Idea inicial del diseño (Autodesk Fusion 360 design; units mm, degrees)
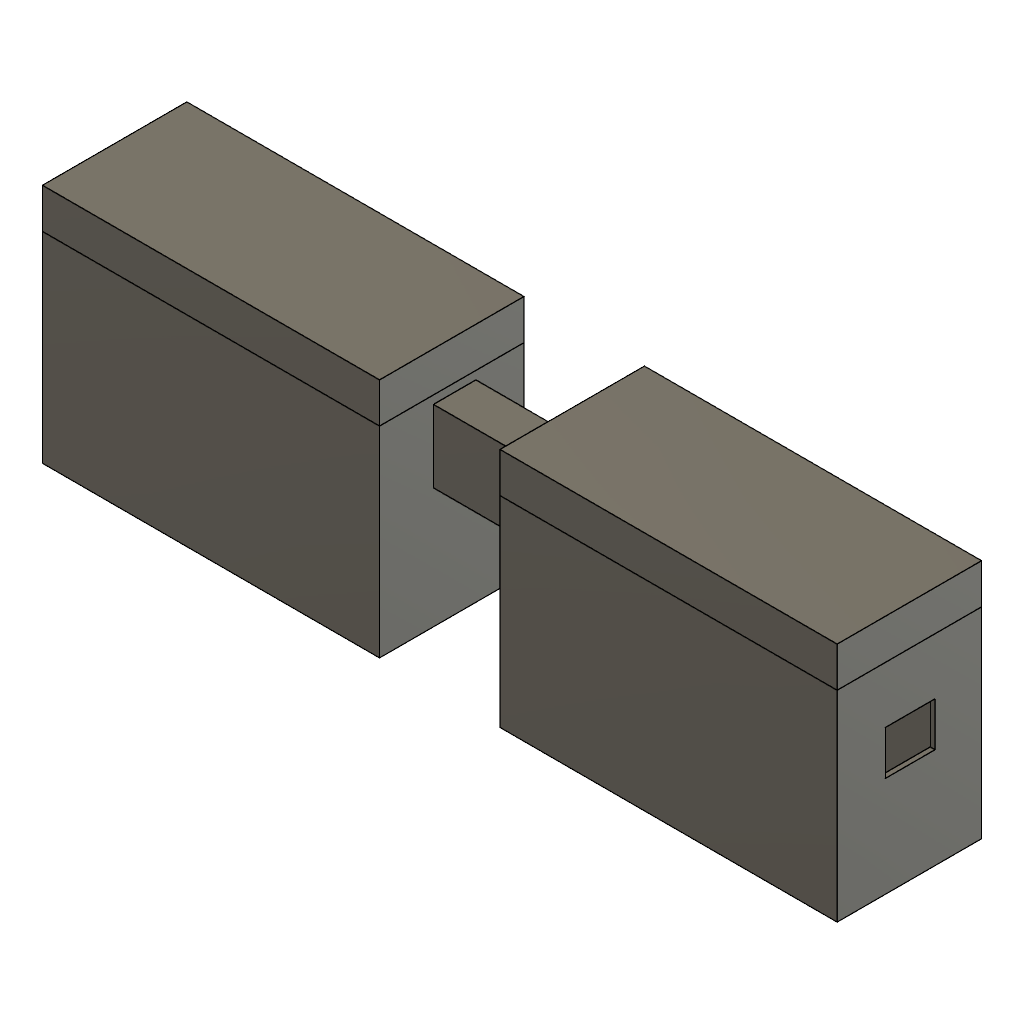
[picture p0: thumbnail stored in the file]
part number: 2026-10-15-12-44-03-142
sketch "Boceto2" plane through (0, 0, 0) normal (0, 0, 1) x axis (1, 0, 0)
  line L1 (40, 30) -> (-30, 30)
  line L2 (40, -20) -> (40, 30)
  line L3 (-30, -20) -> (40, -20)
  line L4 (-30, 30) -> (-30, -20)
  horizontal L1
  vertical L2
  horizontal L3
  vertical L4
extrude "Extruir3" new body sketch "Boceto2" along normal blind 30
move "Desplazar2"
sketch "Boceto4" plane through (40, 0, 0) normal (1, 0, 0) x axis (0, 0, -1)
  line L1 (0, 50) -> (0, 0)
  line L2 (-30, 50) -> (0, 50)
  line L3 (-30, 0) -> (-30, 50)
  line L4 (0, 0) -> (-30, 0)
copy_paste_bodies "CopiarPegarCuerpos"
move "Desplazar3"
sketch "Boceto5" plane through (65, 0, 0) normal (-1, 0, 0) x axis (0, 0, 1)
  line L1 (0, 0) -> (0, 50)
  line L2 (30, 0) -> (0, 0)
  line L3 (30, 50) -> (30, 0)
  line L4 (0, 50) -> (30, 50)
  line L5 (18.8114, 40) -> (10, 40)
  line L6 (18.8114, 25) -> (18.8114, 40)
  line L7 (10, 25) -> (18.8114, 25)
  line L8 (10, 40) -> (10, 25)
  horizontal L5
  vertical L6
  horizontal L7
  vertical L8
shell "Vaciado3" innerThickness 1
shell "Vaciado4" innerThickness 1
sketch "Boceto6" plane through (40, 0, 0) normal (1, 0, 0) x axis (0, 0, -1)
  line L1 (-10, 39.9144) -> (-18.6267, 39.9144)
  line L2 (-10, 25) -> (-10, 39.9144)
  line L3 (-18.6267, 25) -> (-10, 25)
  line L4 (-18.6267, 39.9144) -> (-18.6267, 25)
  horizontal L1
  vertical L2
  horizontal L3
  vertical L4
extrude "Extruir4" cut sketch "Boceto6" along normal blind 35 and against normal blind 10
extrude "Extruir5" new body sketch "Boceto5" profile of L5 L6 L7 L8 along normal blind 25
sketch "Boceto7" plane through (0, 0, 10) normal (0, 0, -1) x axis (-1, 0, 0)
  line L1 (-65, 25) -> (-65, 40)
  line L2 (-40, 25) -> (-65, 25)
  line L3 (-40, 40) -> (-40, 25)
  line L4 (-65, 40) -> (-40, 40)
  line L5 (-48.45, 35) -> (-55, 35)
  line L6 (-48.45, 29.9072) -> (-48.45, 35)
  line L7 (-55, 29.9072) -> (-48.45, 29.9072)
  line L8 (-55, 35) -> (-55, 29.9072)
  horizontal L5
  vertical L6
  horizontal L7
  vertical L8
extrude "Extruir6" cut sketch "Boceto7" profile of L5 L6 L7 L8 along normal blind 5 and against normal blind 5
sketch "Boceto8" plane through (0, 0, 0) normal (0, 0, -1) x axis (-1, 0, 0)
  line L1 (-65, 0) -> (-135, 0)
  line L2 (-65, 50) -> (-65, 0)
  line L3 (-135, 50) -> (-65, 50)
  line L4 (-135, 0) -> (-135, 50)
  curve K1 (36.9063, 41.702) -> (-135, 41.702)
  point P6 (-135, 41.702)
  coincident L4 P6
split "Dividir"
sketch "Boceto9" plane through (-30, 0, 0) normal (-1, 0, 0) x axis (0, 0, 1)
  line L1 (0, 41.702) -> (30, 41.702)
  line L2 (0, 0) -> (0, 41.702)
  line L3 (30, 0) -> (0, 0)
  line L4 (30, 41.702) -> (30, 0)
  line L5 (20, 30) -> (10, 30)
  line L6 (20, 20) -> (20, 30)
  line L7 (10, 20) -> (20, 20)
  line L8 (10, 30) -> (10, 20)
  horizontal L5
  vertical L6
  horizontal L7
  vertical L8
sketch "Boceto10" plane through (135, 0, 0) normal (1, 0, 0) x axis (0, 0, -1)
  line L1 (-30, 41.702) -> (0, 41.702)
  line L2 (-30, 0) -> (-30, 41.702)
  line L3 (0, 0) -> (-30, 0)
  line L4 (0, 41.702) -> (0, 0)
  line L5 (-9.6731, 30) -> (-20, 30)
  line L6 (-9.6731, 20.851) -> (-9.6731, 30)
  line L7 (-20, 20.851) -> (-9.6731, 20.851)
  line L8 (-20, 30) -> (-20, 20.851)
  horizontal L5
  vertical L6
  horizontal L7
  vertical L8
sketch "Boceto11" plane through (40, 0, 0) normal (-1, 0, 0) x axis (0, 0, 1)
  line L1 (18.8114, 25) -> (10, 25)
  line L2 (18.8114, 40) -> (18.8114, 25)
  line L3 (10, 40) -> (18.8114, 40)
  line L4 (10, 25) -> (10, 40)
  line L5 (16.8952, 37.4381) -> (12.0954, 37.4381)
  line L6 (16.8952, 27.2626) -> (16.8952, 37.4381)
  line L7 (12.0954, 27.2626) -> (16.8952, 27.2626)
  line L8 (12.0954, 37.4381) -> (12.0954, 27.2626)
  horizontal L5
  vertical L6
  horizontal L7
  vertical L8
extrude "Extruir7" cut sketch "Boceto11" profile of L5 L6 L7 L8 along normal blind 10 and against normal blind 30
extrude "Extruir8" cut sketch "Boceto10" profile of L5 L6 L7 L8 along normal blind 5 and against normal blind 5
extrude "Extruir9" cut sketch "Boceto9" profile of L5 L6 L7 L8 along normal blind 10 and against normal blind 5
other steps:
base_feature "Elemento base"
